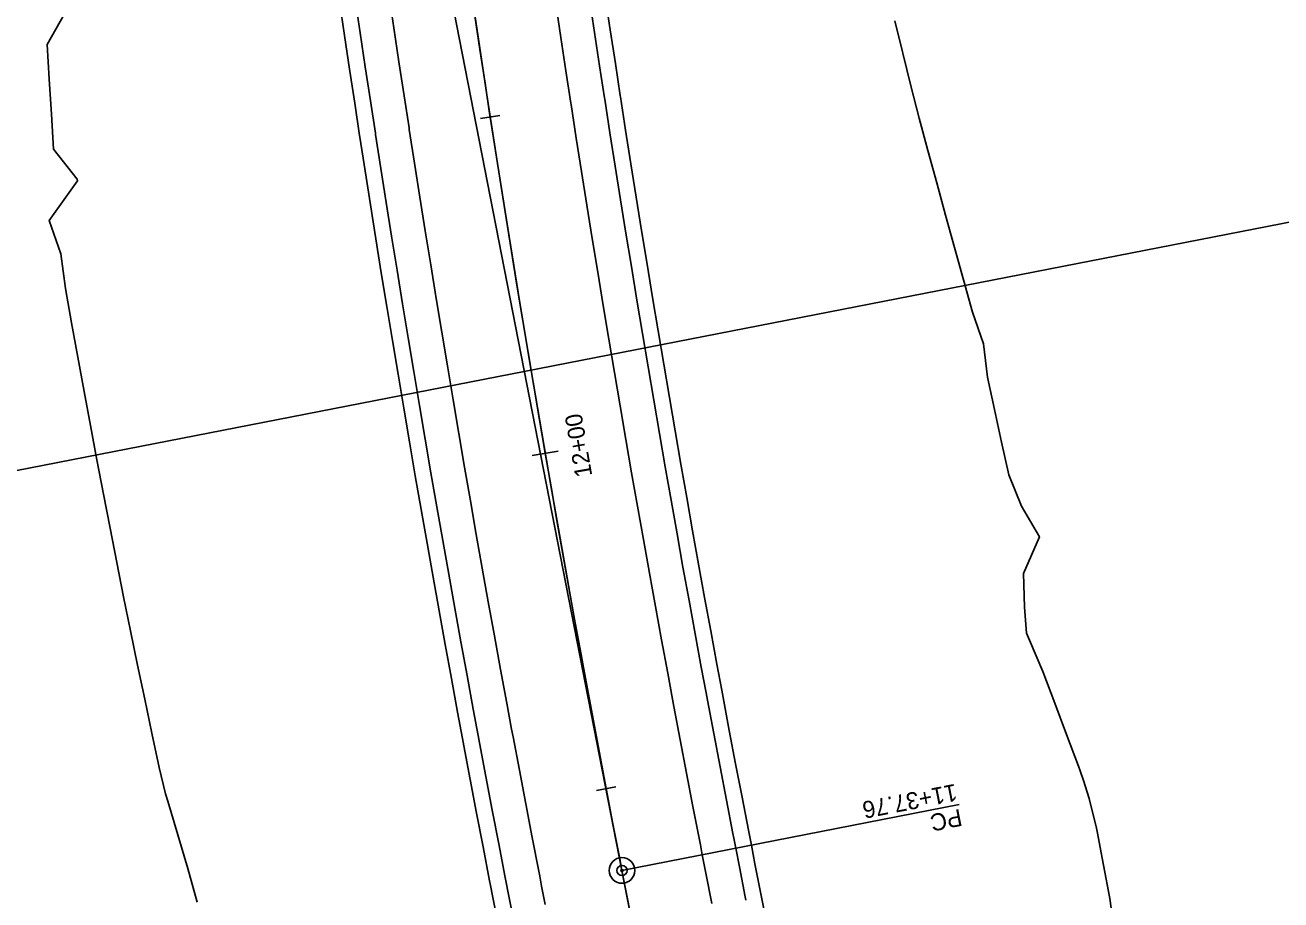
# Model space of a CAD drawing. Extents: x 1150550 to 1151113, y 1141187 to 1143500.
# Drawn here: x 1150688.9 to 1150873.1, y 1142116.1 to 1142244.5 of the extents above; entities that cross this region are included whole.
import ezdxf

# ---------------------------------------------------------------- set-up
doc = ezdxf.new("R2010")
doc.units = 0
for name, color, linetype in [('AC_P', 7, 'Continuous'), ('ACSC_P_T', 7, 'Continuous'), ('ACSCT_P', 7, 'Continuous'), ('ACSR_P_T', 7, 'Continuous'), ('ACSRT_P', 7, 'Continuous'), ('ADEFAULT', 7, 'Continuous'), ('Default', 7, 'Continuous'), ('LELB_P', 7, 'Continuous'), ('LFILL_P', 7, 'Continuous'), ('PE_P', 7, 'Continuous'), ('PET_P', 7, 'Continuous'), ('XSCTOP1_P', 7, 'Continuous')]:
    doc.layers.add(name, color=color, linetype=linetype)

msp = doc.modelspace()

# ---------------------------------------------------------------- linework, layer by layer
at = {"layer": 'AC_P'}
msp.add_line((1150819.56, 1141899.84), (1150776.47, 1142120.43), dxfattribs=at)
msp.add_lwpolyline([(1150777.86, 1142113.3), (1150777, 1142117.72), (1150776.47, 1142120.43), (1150776.18, 1142121.91), (1150776.04, 1142122.63), (1150775.09, 1142127.53), (1150774.15, 1142132.44), (1150773.22, 1142137.36), (1150772.29, 1142142.27), (1150772.09, 1142143.35), (1150771.38, 1142147.19), (1150770.47, 1142152.1), (1150769.57, 1142157.02), (1150768.68, 1142161.94), (1150767.8, 1142166.86), (1150766.93, 1142171.79), (1150766.07, 1142176.71), (1150765.21, 1142181.64), (1150764.36, 1142186.57), (1150763.53, 1142191.5), (1150762.7, 1142196.43), (1150761.88, 1142201.36), (1150761.07, 1142206.29), (1150760.27, 1142211.23), (1150759.47, 1142216.16), (1150758.69, 1142221.1), (1150757.91, 1142226.04), (1150757.14, 1142230.98), (1150757.11, 1142231.2), (1150756.39, 1142235.93), (1150755.64, 1142240.87), (1150754.89, 1142245.81)], dxfattribs=at)
msp.add_arc((1153549.06, 1142662.07), 2825, 166.27261, 191.05386, dxfattribs=at)
at = {"layer": 'ACSCT_P'}
msp.add_lwpolyline([(1150776.47, 1142120.43), (1150825.93, 1142130.09)], dxfattribs=at)
at = {"layer": 'ACSRT_P'}
for points in [[(1150755.72, 1142230.76), (1150758.57, 1142231.2)], [(1150763.32, 1142181.31), (1150767.1, 1142181.97)], [(1150772.74, 1142132.17), (1150775.56, 1142132.71)]]:
    msp.add_lwpolyline(points, dxfattribs=at)
at = {"layer": 'ADEFAULT'}
for radius in [1.88, 0.747, 0.156]:
    msp.add_circle((1150776.47, 1142120.43), radius, dxfattribs=at)
at = {"layer": 'Default'}
msp.add_line((1150956.27, 1141200.06), (1150657.48, 1142729.55), dxfattribs=at)
msp.add_lwpolyline([(1150982.27, 1142236.63), (1151112.58, 1141569.23), (1150680.73, 1141484.91), (1150550.43, 1142152.31)], close=True, dxfattribs=at)
at = {"layer": 'LELB_P'}
for points in [[(1150758.02, 1142114.01), (1150757.5, 1142116.72), (1150757.2, 1142118.21), (1150757.06, 1142118.93), (1150756.11, 1142123.88), (1150755.16, 1142128.82), (1150754.22, 1142133.77), (1150753.29, 1142138.71), (1150753.09, 1142139.8), (1150752.37, 1142143.66), (1150751.45, 1142148.61), (1150750.55, 1142153.57), (1150749.65, 1142158.52), (1150748.77, 1142163.48), (1150747.89, 1142168.43), (1150747.02, 1142173.39), (1150746.16, 1142178.35), (1150745.31, 1142183.31), (1150744.46, 1142188.28), (1150743.63, 1142193.24), (1150742.8, 1142198.21), (1150741.99, 1142203.17), (1150741.18, 1142208.14), (1150740.38, 1142213.11), (1150739.59, 1142218.09), (1150738.81, 1142223.06), (1150738.04, 1142228.03), (1150738, 1142228.25), (1150737.27, 1142233.01), (1150736.52, 1142237.99), (1150735.77, 1142242.96), (1150735.03, 1142247.94)], [(1150797.89, 1142111.61), (1150796.93, 1142116.52), (1150796.84, 1142117.01), (1150795.97, 1142121.42), (1150795.44, 1142124.14), (1150795.16, 1142125.61), (1150795.02, 1142126.32), (1150794.08, 1142131.19), (1150793.14, 1142136.07), (1150792.21, 1142140.95), (1150791.3, 1142145.83), (1150791.09, 1142146.9), (1150790.39, 1142150.71), (1150789.49, 1142155.59), (1150788.59, 1142160.48), (1150787.71, 1142165.36), (1150786.83, 1142170.25), (1150785.97, 1142175.14), (1150785.11, 1142180.03), (1150784.26, 1142184.93), (1150783.42, 1142189.82), (1150782.59, 1142194.72), (1150781.77, 1142199.61), (1150780.95, 1142204.51), (1150780.15, 1142209.41), (1150779.35, 1142214.31), (1150778.56, 1142219.22), (1150777.78, 1142224.12), (1150777.01, 1142229.03), (1150776.25, 1142233.93), (1150776.22, 1142234.15), (1150775.5, 1142238.84), (1150774.75, 1142243.75), (1150774.02, 1142248.66)], [(1150714.17, 1142115.8), (1150712.81, 1142120.74), (1150711.35, 1142125.66), (1150709.85, 1142130.58), (1150709.52, 1142131.67), (1150708.61, 1142135.55), (1150707.54, 1142140.55), (1150706.48, 1142145.56), (1150705.44, 1142150.57), (1150704.41, 1142155.58), (1150703.39, 1142160.59), (1150702.39, 1142165.61), (1150701.4, 1142170.63), (1150700.43, 1142175.65), (1150699.47, 1142180.67), (1150698.52, 1142185.7), (1150697.59, 1142190.73), (1150696.66, 1142195.76), (1150695.75, 1142200.8), (1150694.86, 1142205.84), (1150694.17, 1142210.91), (1150692.46, 1142215.82), (1150696.61, 1142221.64), (1150696.59, 1142221.86), (1150693.11, 1142226.27), (1150692.79, 1142231.39), (1150692.47, 1142236.51), (1150692.17, 1142241.64), (1150695.36, 1142247.26)], [(1150816.47, 1142245.09), (1150817.6, 1142240.54), (1150817.65, 1142240.33), (1150818.85, 1142235.56), (1150820.04, 1142230.8), (1150821.33, 1142226.05), (1150822.63, 1142221.31), (1150823.93, 1142216.57), (1150825.24, 1142211.83), (1150826.56, 1142207.1), (1150827.89, 1142202.37), (1150829.46, 1142197.68), (1150830.06, 1142192.83), (1150831.1, 1142188.05), (1150832.13, 1142183.28), (1150833.18, 1142178.5), (1150835.08, 1142173.89), (1150837.68, 1142169.4), (1150835.37, 1142164.01), (1150835.49, 1142159.07), (1150835.81, 1142155.26), (1150836.24, 1142154.24), (1150838.2, 1142149.64), (1150839.93, 1142145), (1150841.66, 1142140.36), (1150843.41, 1142135.73), (1150843.66, 1142135.05), (1150844.17, 1142133.65), (1150844.97, 1142131), (1150846.05, 1142126.62), (1150846.14, 1142126.13), (1150847.08, 1142121.22), (1150848.01, 1142116.31), (1150848.69, 1142111.35)]]:
    msp.add_lwpolyline(points, dxfattribs=at)
at = {"layer": 'LFILL_P'}
for points in [[(1150714.17, 1142115.8), (1150712.81, 1142120.74), (1150711.35, 1142125.66), (1150709.85, 1142130.58), (1150709.52, 1142131.67), (1150708.61, 1142135.55), (1150707.54, 1142140.55), (1150706.48, 1142145.56), (1150705.44, 1142150.57), (1150704.41, 1142155.58), (1150703.39, 1142160.59), (1150702.39, 1142165.61), (1150701.4, 1142170.63), (1150700.43, 1142175.65), (1150699.47, 1142180.67), (1150698.52, 1142185.7), (1150697.59, 1142190.73), (1150696.66, 1142195.76), (1150695.75, 1142200.8), (1150694.86, 1142205.84), (1150694.17, 1142210.91), (1150692.46, 1142215.82), (1150696.61, 1142221.64), (1150696.59, 1142221.86), (1150693.11, 1142226.27), (1150692.79, 1142231.39), (1150692.47, 1142236.51), (1150692.17, 1142241.64), (1150695.36, 1142247.26)], [(1150848.69, 1142111.35), (1150848.01, 1142116.31), (1150847.08, 1142121.22), (1150846.14, 1142126.13), (1150846.05, 1142126.62), (1150844.97, 1142131), (1150844.17, 1142133.65), (1150843.66, 1142135.05), (1150843.41, 1142135.73), (1150841.66, 1142140.36), (1150839.93, 1142145), (1150838.2, 1142149.64), (1150836.24, 1142154.24), (1150835.81, 1142155.26), (1150835.49, 1142159.07), (1150835.37, 1142164.01), (1150837.68, 1142169.4), (1150835.08, 1142173.89), (1150833.18, 1142178.5), (1150832.13, 1142183.28), (1150831.1, 1142188.05), (1150830.06, 1142192.83), (1150829.46, 1142197.68), (1150827.89, 1142202.37), (1150826.56, 1142207.1), (1150825.24, 1142211.83), (1150823.93, 1142216.57), (1150822.63, 1142221.31), (1150821.33, 1142226.05), (1150820.04, 1142230.8), (1150818.85, 1142235.56), (1150817.65, 1142240.33), (1150817.6, 1142240.54), (1150816.47, 1142245.09)]]:
    msp.add_lwpolyline(points, dxfattribs=at)
at = {"layer": 'PE_P'}
for points in [[(1150760.31, 1142114.46), (1150759.79, 1142117.17), (1150759.49, 1142118.66), (1150759.35, 1142119.38), (1150758.4, 1142124.32), (1150757.45, 1142129.26), (1150756.51, 1142134.2), (1150755.58, 1142139.14), (1150755.38, 1142140.23), (1150754.66, 1142144.09), (1150753.75, 1142149.03), (1150752.85, 1142153.98), (1150751.95, 1142158.93), (1150751.06, 1142163.88), (1150750.19, 1142168.84), (1150749.32, 1142173.79), (1150748.46, 1142178.75), (1150747.61, 1142183.71), (1150746.77, 1142188.66), (1150745.93, 1142193.62), (1150745.11, 1142198.59), (1150744.29, 1142203.55), (1150743.48, 1142208.52), (1150742.69, 1142213.48), (1150741.9, 1142218.45), (1150741.12, 1142223.42), (1150740.34, 1142228.39), (1150740.31, 1142228.61), (1150739.58, 1142233.36), (1150738.83, 1142238.33), (1150738.08, 1142243.31), (1150737.34, 1142248.28)], [(1150794.64, 1142116.07), (1150794.55, 1142116.56), (1150793.68, 1142120.98), (1150793.15, 1142123.69), (1150792.87, 1142125.16), (1150792.73, 1142125.87), (1150791.78, 1142130.75), (1150790.85, 1142135.63), (1150789.92, 1142140.51), (1150789, 1142145.4), (1150788.8, 1142146.47), (1150788.09, 1142150.28), (1150787.19, 1142155.17), (1150786.3, 1142160.06), (1150785.41, 1142164.95), (1150784.54, 1142169.84), (1150783.67, 1142174.74), (1150782.81, 1142179.63), (1150781.96, 1142184.53), (1150781.12, 1142189.43), (1150780.29, 1142194.33), (1150779.47, 1142199.23), (1150778.65, 1142204.13), (1150777.85, 1142209.04), (1150777.05, 1142213.94), (1150776.26, 1142218.85), (1150775.48, 1142223.76), (1150774.71, 1142228.67), (1150773.94, 1142233.58), (1150773.91, 1142233.8), (1150773.19, 1142238.49), (1150772.45, 1142243.4), (1150771.71, 1142248.32)]]:
    msp.add_lwpolyline(points, dxfattribs=at)
at = {"layer": 'PET_P'}
for points in [[(1150765.22, 1142115.42), (1150764.69, 1142118.13), (1150764.4, 1142119.61), (1150764.26, 1142120.33), (1150763.31, 1142125.26), (1150762.36, 1142130.2), (1150761.43, 1142135.13), (1150760.5, 1142140.06), (1150760.29, 1142141.15), (1150759.58, 1142145), (1150758.67, 1142149.94), (1150757.76, 1142154.88), (1150756.87, 1142159.82), (1150755.99, 1142164.76), (1150755.11, 1142169.7), (1150754.24, 1142174.65), (1150753.39, 1142179.6), (1150752.54, 1142184.55), (1150751.7, 1142189.5), (1150750.86, 1142194.45), (1150750.04, 1142199.4), (1150749.23, 1142204.36), (1150748.42, 1142209.31), (1150747.62, 1142214.27), (1150746.83, 1142219.23), (1150746.06, 1142224.19), (1150745.28, 1142229.15), (1150745.25, 1142229.37), (1150744.52, 1142234.11), (1150743.77, 1142239.08), (1150743.03, 1142244.05), (1150742.29, 1142249.01)], [(1150789.64, 1142115.6), (1150788.78, 1142120.02), (1150788.25, 1142122.73), (1150787.96, 1142124.2), (1150787.82, 1142124.92), (1150786.87, 1142129.8), (1150785.94, 1142134.69), (1150785.01, 1142139.59), (1150784.09, 1142144.48), (1150783.89, 1142145.56), (1150783.18, 1142149.37), (1150782.27, 1142154.27), (1150781.38, 1142159.17), (1150780.49, 1142164.07), (1150779.62, 1142168.97), (1150778.75, 1142173.87), (1150777.89, 1142178.77), (1150777.04, 1142183.68), (1150776.19, 1142188.59), (1150775.36, 1142193.49), (1150774.53, 1142198.4), (1150773.72, 1142203.32), (1150772.91, 1142208.23), (1150772.11, 1142213.14), (1150771.32, 1142218.06), (1150770.54, 1142222.98), (1150769.77, 1142227.89), (1150769, 1142232.81), (1150768.97, 1142233.03), (1150768.25, 1142237.74), (1150767.5, 1142242.66), (1150766.76, 1142247.58)]]:
    msp.add_lwpolyline(points, dxfattribs=at)
at = {"layer": 'XSCTOP1_P'}
for points in [[(1150760.31, 1142114.46), (1150759.79, 1142117.17), (1150759.49, 1142118.66), (1150759.35, 1142119.38), (1150758.4, 1142124.32), (1150757.45, 1142129.26), (1150756.51, 1142134.2), (1150755.58, 1142139.14), (1150755.38, 1142140.23), (1150754.66, 1142144.09), (1150753.75, 1142149.03), (1150752.85, 1142153.98), (1150751.95, 1142158.93), (1150751.06, 1142163.88), (1150750.19, 1142168.84), (1150749.32, 1142173.79), (1150748.46, 1142178.75), (1150747.61, 1142183.71), (1150746.77, 1142188.66), (1150745.93, 1142193.62), (1150745.11, 1142198.59), (1150744.29, 1142203.55), (1150743.48, 1142208.52), (1150742.69, 1142213.48), (1150741.9, 1142218.45), (1150741.12, 1142223.42), (1150740.34, 1142228.39), (1150740.31, 1142228.61), (1150739.58, 1142233.36), (1150738.83, 1142238.33), (1150738.08, 1142243.31), (1150737.34, 1142248.28)], [(1150765.22, 1142115.42), (1150764.69, 1142118.13), (1150764.4, 1142119.61), (1150764.26, 1142120.33), (1150763.31, 1142125.26), (1150762.36, 1142130.2), (1150761.43, 1142135.13), (1150760.5, 1142140.06), (1150760.29, 1142141.15), (1150759.58, 1142145), (1150758.67, 1142149.94), (1150757.76, 1142154.88), (1150756.87, 1142159.82), (1150755.99, 1142164.76), (1150755.11, 1142169.7), (1150754.24, 1142174.65), (1150753.39, 1142179.6), (1150752.54, 1142184.55), (1150751.7, 1142189.5), (1150750.86, 1142194.45), (1150750.04, 1142199.4), (1150749.23, 1142204.36), (1150748.42, 1142209.31), (1150747.62, 1142214.27), (1150746.83, 1142219.23), (1150746.06, 1142224.19), (1150745.28, 1142229.15), (1150745.25, 1142229.37), (1150744.52, 1142234.11), (1150743.77, 1142239.08), (1150743.03, 1142244.05), (1150742.29, 1142249.01)], [(1150789.64, 1142115.6), (1150788.78, 1142120.02), (1150788.25, 1142122.73), (1150787.96, 1142124.2), (1150787.82, 1142124.92), (1150786.87, 1142129.8), (1150785.94, 1142134.69), (1150785.01, 1142139.59), (1150784.09, 1142144.48), (1150783.89, 1142145.56), (1150783.18, 1142149.37), (1150782.27, 1142154.27), (1150781.38, 1142159.17), (1150780.49, 1142164.07), (1150779.62, 1142168.97), (1150778.75, 1142173.87), (1150777.89, 1142178.77), (1150777.04, 1142183.68), (1150776.19, 1142188.59), (1150775.36, 1142193.49), (1150774.53, 1142198.4), (1150773.72, 1142203.32), (1150772.91, 1142208.23), (1150772.11, 1142213.14), (1150771.32, 1142218.06), (1150770.54, 1142222.98), (1150769.77, 1142227.89), (1150769, 1142232.81), (1150768.97, 1142233.03), (1150768.25, 1142237.74), (1150767.5, 1142242.66), (1150766.76, 1142247.58)], [(1150794.64, 1142116.07), (1150794.55, 1142116.56), (1150793.68, 1142120.98), (1150793.15, 1142123.69), (1150792.87, 1142125.16), (1150792.73, 1142125.87), (1150791.78, 1142130.75), (1150790.85, 1142135.63), (1150789.92, 1142140.51), (1150789, 1142145.4), (1150788.8, 1142146.47), (1150788.09, 1142150.28), (1150787.19, 1142155.17), (1150786.3, 1142160.06), (1150785.41, 1142164.95), (1150784.54, 1142169.84), (1150783.67, 1142174.74), (1150782.81, 1142179.63), (1150781.96, 1142184.53), (1150781.12, 1142189.43), (1150780.29, 1142194.33), (1150779.47, 1142199.23), (1150778.65, 1142204.13), (1150777.85, 1142209.04), (1150777.05, 1142213.94), (1150776.26, 1142218.85), (1150775.48, 1142223.76), (1150774.71, 1142228.67), (1150773.94, 1142233.58), (1150773.91, 1142233.8), (1150773.19, 1142238.49), (1150772.45, 1142243.4), (1150771.71, 1142248.32)], [(1150777.86, 1142113.3), (1150777, 1142117.72), (1150776.47, 1142120.43), (1150776.18, 1142121.91), (1150776.04, 1142122.63), (1150775.09, 1142127.53), (1150774.15, 1142132.44), (1150773.22, 1142137.36), (1150772.29, 1142142.27), (1150772.09, 1142143.35), (1150771.38, 1142147.19), (1150770.47, 1142152.1), (1150769.57, 1142157.02), (1150768.68, 1142161.94), (1150767.8, 1142166.86), (1150766.93, 1142171.79), (1150766.07, 1142176.71), (1150765.21, 1142181.64), (1150764.36, 1142186.57), (1150763.53, 1142191.5), (1150762.7, 1142196.43), (1150761.88, 1142201.36), (1150761.07, 1142206.29), (1150760.27, 1142211.23), (1150759.47, 1142216.16), (1150758.69, 1142221.1), (1150757.91, 1142226.04), (1150757.14, 1142230.98), (1150757.11, 1142231.2), (1150756.39, 1142235.93), (1150755.64, 1142240.87), (1150754.89, 1142245.81)]]:
    msp.add_lwpolyline(points, dxfattribs=at)

# ---------------------------------------------------------------- texts
at = {"layer": 'ACSC_P_T'}
for s, p in [('11+37.76', (1150825.34, 1142133.16)), ('PC', (1150826.05, 1142129.48))]:
    msp.add_text(s, height=2.501, rotation=191.0539, dxfattribs=at).set_placement(p)
at = {"layer": 'ACSR_P_T'}
msp.add_text('12+00', height=2.501, rotation=99.7916, dxfattribs=at).set_placement((1150772.12, 1142178.36))

doc.saveas('drawing.dxf')
